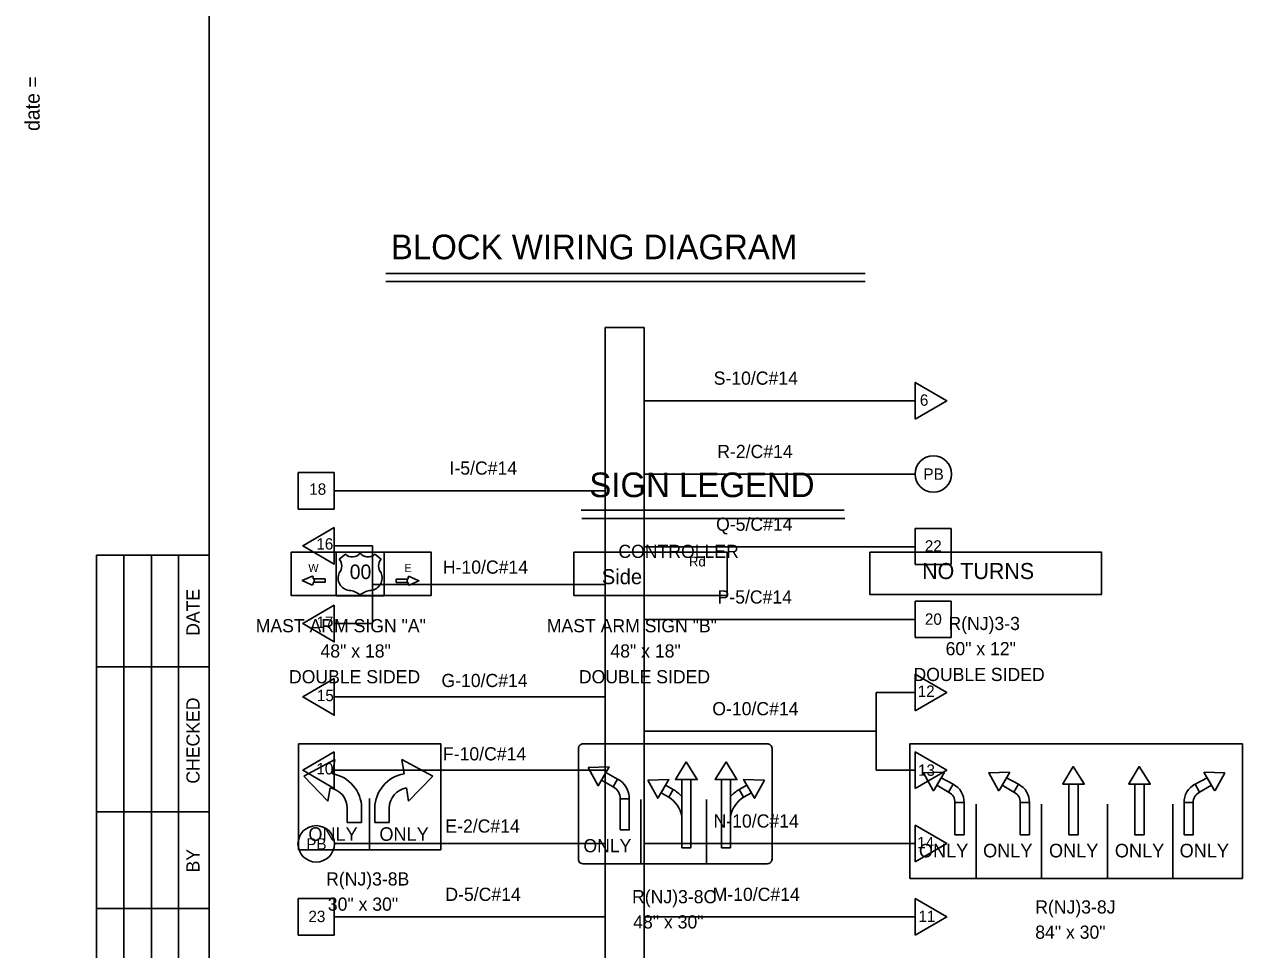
# Model space of a CAD drawing. Extents: x 488740 to 507913, y 466518 to 497949.
# Drawn here: x 507907.771 to 507908.469, y 496046.789 to 496047.319 of the extents above; entities that cross this region are included whole.
import ezdxf

# ---------------------------------------------------------------- set-up
doc = ezdxf.new("R2010")
doc.units = 0
for name, color, linetype in [('1', 7, 'Continuous'), ('25', 7, 'Continuous'), ('38', 7, 'Continuous'), ('9', 7, 'Continuous')]:
    doc.layers.add(name, color=color, linetype=linetype)

msp = doc.modelspace()

# ---------------------------------------------------------------- linework, layer by layer
at = {"layer": '1'}
for p, q in [((507907.8773, 496048.19783), (507907.8773, 496046.44783)), ((507907.8773, 496046.95965), (507907.8773, 496047.01542))]:
    msp.add_line(p, q, dxfattribs=at)
at = {"layer": '25'}
for p, q in [((507907.8773, 496047.01542), (507907.81266, 496047.01542)), ((507907.81266, 496046.44783), (507907.81266, 496047.01542)), ((507907.82841, 496046.44783), (507907.82841, 496047.01542)), ((507907.84416, 496046.44783), (507907.84416, 496047.01542)), ((507907.85958, 496046.44783), (507907.85958, 496047.01542)), ((507907.8773, 496046.95144), (507907.81266, 496046.95144)), ((507907.8773, 496046.86844), (507907.81266, 496046.86844)), ((507907.8773, 496046.81299), (507907.81266, 496046.81299))]:
    msp.add_line(p, q, dxfattribs=at)
at = {"layer": '38'}
for p, q in [((507908.0902, 496047.04115), (507908.24079, 496047.04115)), ((507908.09066, 496047.03646), (507908.24126, 496047.03646)), ((507908.08598, 496047.01712), (507908.08598, 496046.99219)), ((507908.08598, 496047.01712), (507908.17391, 496047.01712)), ((507908.08598, 496047.01712), (507908.17391, 496047.01712)), ((507908.17391, 496047.01712), (507908.17391, 496046.99219)), ((507907.95171, 496047.01307), (507907.95526, 496047.01587)), ((507907.97209, 496047.01587), (507907.97565, 496047.01307)), ((507907.96358, 496046.99215), (507907.96358, 496046.99272)), ((507907.96378, 496046.99272), (507907.96378, 496046.99215)), ((507908.08598, 496046.99219), (507908.17391, 496046.99219)), ((507907.92844, 496046.90724), (507907.92844, 496046.84654)), ((507907.92844, 496046.90724), (507908.0098, 496046.90724)), ((507908.0098, 496046.90724), (507908.0098, 496046.84654)), ((507908.08876, 496046.90497), (507908.08876, 496046.8412)), ((507908.0915, 496046.90724), (507908.19681, 496046.90724)), ((507908.19956, 496046.90465), (507908.19956, 496046.8412)), ((507908.27839, 496046.90727), (507908.46901, 496046.90727)), ((507908.27839, 496046.90727), (507908.27839, 496046.83017)), ((507908.46901, 496046.90727), (507908.46901, 496046.83017)), ((507907.9491, 496046.89839), (507907.93139, 496046.88888)), ((507907.94779, 496046.89019), (507907.9491, 496046.89839)), ((507907.9888, 496046.89019), (507907.98749, 496046.89839)), ((507907.98749, 496046.89839), (507908.00521, 496046.88888)), ((507907.93139, 496046.88888), (507907.94517, 496046.87444)), ((507908.00521, 496046.88888), (507907.99143, 496046.87444)), ((507908.10849, 496046.88272), (507908.11103, 496046.88717)), ((507908.30067, 496046.87959), (507908.30328, 496046.88416)), ((507908.33807, 496046.87959), (507908.34068, 496046.88416)), ((507908.44434, 496046.87959), (507908.44173, 496046.88416)), ((507907.94517, 496046.87444), (507907.94644, 496046.8821)), ((507907.99143, 496046.87444), (507907.99015, 496046.8821)), ((507908.14039, 496046.87677), (507908.14293, 496046.88122)), ((507908.14787, 496046.8771), (507908.14787, 496046.86576)), ((507908.1758, 496046.8771), (507908.1758, 496046.86576)), ((507908.18328, 496046.87677), (507908.18073, 496046.88122)), ((507907.95632, 496046.87051), (507907.95632, 496046.86231)), ((507907.96452, 496046.86231), (507907.96452, 496046.87051)), ((507907.96912, 496046.84654), (507907.96912, 496046.87607)), ((507907.97207, 496046.86231), (507907.97207, 496046.87051)), ((507907.98027, 496046.87051), (507907.98027, 496046.86231)), ((507908.11775, 496046.87576), (507908.11262, 496046.87576)), ((507908.12431, 496046.83867), (507908.12431, 496046.87541)), ((507908.16203, 496046.83867), (507908.16203, 496046.87541)), ((507908.30951, 496046.87366), (507908.30426, 496046.87366)), ((507908.31645, 496046.83017), (507908.31645, 496046.87282)), ((507908.34691, 496046.87366), (507908.34166, 496046.87366)), ((507908.35385, 496046.83017), (507908.35385, 496046.87282)), ((507908.39158, 496046.83017), (507908.39158, 496046.87282)), ((507908.42898, 496046.83017), (507908.42898, 496046.87282)), ((507908.43549, 496046.87366), (507908.44074, 496046.87366)), ((507908.27839, 496046.86856), (507908.27839, 496046.86856)), ((507907.95632, 496046.86231), (507907.96452, 496046.86231)), ((507907.98027, 496046.86231), (507907.97207, 496046.86231)), ((507907.92844, 496046.84654), (507908.0098, 496046.84654)), ((507908.09117, 496046.83867), (507908.19681, 496046.83867)), ((507908.27839, 496046.83017), (507908.46901, 496046.83017))]:
    msp.add_line(p, q, dxfattribs=at)
for points in [[(507907.92424, 496047.01712), (507908.00429, 496047.01712), (507908.00429, 496046.99219), (507907.92424, 496046.99219)], [(507908.2556, 496047.01712), (507908.38815, 496047.01712), (507908.38815, 496046.99284), (507908.2556, 496046.99284)], [(507907.93732, 496046.99984), (507907.93726, 496046.99984), (507907.93709, 496046.99984), (507907.93698, 496046.99978), (507907.93681, 496046.99972), (507907.93676, 496046.99967), (507907.93676, 496046.99961), (507907.9367, 496046.99866), (507907.9367, 496046.9986), (507907.93664, 496046.99854), (507907.93659, 496046.99849), (507907.93648, 496046.99843), (507907.93642, 496046.99843), (507907.93631, 496046.99832), (507907.93614, 496046.99832), (507907.93597, 496046.99832), (507907.93574, 496046.99843), (507907.93057, 496047.00079), (507907.93591, 496047.00316), (507907.93597, 496047.00321), (507907.93614, 496047.00327), (507907.93631, 496047.00327), (507907.93648, 496047.00321), (507907.93659, 496047.00316), (507907.9367, 496047.0031), (507907.93676, 496047.00299), (507907.93681, 496047.00293), (507907.93681, 496047.00203), (507907.93681, 496047.00192), (507907.93681, 496047.00186), (507907.93693, 496047.00181), (507907.93693, 496047.00181), (507907.93698, 496047.00175), (507907.93709, 496047.00175), (507907.93709, 496047.00175), (507907.93738, 496047.00175)], [(507907.99062, 496046.9998), (507907.99068, 496046.9998), (507907.99084, 496046.9998), (507907.99096, 496046.99974), (507907.99113, 496046.99969), (507907.99118, 496046.99963), (507907.99118, 496046.99957), (507907.99124, 496046.99862), (507907.99124, 496046.99856), (507907.99129, 496046.99851), (507907.99135, 496046.99845), (507907.99146, 496046.99839), (507907.99152, 496046.99839), (507907.99163, 496046.99828), (507907.9918, 496046.99828), (507907.99197, 496046.99828), (507907.99219, 496046.99839), (507907.99737, 496047.00076), (507907.99203, 496047.00312), (507907.99197, 496047.00317), (507907.9918, 496047.00323), (507907.99163, 496047.00323), (507907.99146, 496047.00317), (507907.99135, 496047.00312), (507907.99124, 496047.00306), (507907.99118, 496047.00295), (507907.99113, 496047.00289), (507907.99113, 496047.00199), (507907.99113, 496047.00188), (507907.99113, 496047.00182), (507907.99101, 496047.00177), (507907.99101, 496047.00177), (507907.99096, 496047.00171), (507907.99084, 496047.00171), (507907.99084, 496047.00171), (507907.99056, 496047.00171)], [(507907.93738, 496046.99984), (507907.94356, 496046.99984), (507907.94356, 496047.00175), (507907.93738, 496047.00175)], [(507907.99056, 496046.9998), (507907.98438, 496046.9998), (507907.98438, 496047.00171), (507907.99056, 496047.00171)], [(507908.09425, 496046.8938), (507908.09998, 496046.88335), (507908.10626, 496046.89413)], [(507908.10185, 496046.88651), (507908.10439, 496046.89096), (507908.11103, 496046.88717), (507908.10849, 496046.88272)], [(507908.15035, 496046.89708), (507908.14419, 496046.88687), (507908.15667, 496046.88686)], [(507908.17332, 496046.89708), (507908.17947, 496046.88687), (507908.16699, 496046.88686)], [(507908.29212, 496046.88055), (507908.29179, 496046.88055), (507908.28622, 496046.89072), (507908.29803, 496046.89105), (507908.29803, 496046.89072)], [(507908.32952, 496046.88055), (507908.3292, 496046.88055), (507908.32362, 496046.89072), (507908.33543, 496046.89105), (507908.33543, 496046.89072)], [(507908.36611, 496046.88415), (507908.36611, 496046.88448), (507908.37202, 496046.89433), (507908.37825, 496046.88448), (507908.37825, 496046.88415)], [(507908.40383, 496046.88415), (507908.40383, 496046.88448), (507908.40973, 496046.89433), (507908.41597, 496046.88448), (507908.41597, 496046.88415)], [(507908.45288, 496046.88055), (507908.45321, 496046.88055), (507908.45879, 496046.89072), (507908.44698, 496046.89105), (507908.44698, 496046.89072)], [(507908.12837, 496046.88658), (507908.1341, 496046.87613), (507908.14038, 496046.88691)], [(507908.13597, 496046.87929), (507908.13851, 496046.88375), (507908.14293, 496046.88122), (507908.14039, 496046.87677)], [(507908.14787, 496046.84787), (507908.153, 496046.84787), (507908.153, 496046.88686), (507908.14787, 496046.88686)], [(507908.1758, 496046.84787), (507908.17067, 496046.84787), (507908.17067, 496046.88686), (507908.1758, 496046.88686)], [(507908.1877, 496046.87929), (507908.18515, 496046.88375), (507908.18073, 496046.88122), (507908.18328, 496046.87677)], [(507908.1953, 496046.88658), (507908.18957, 496046.87613), (507908.18328, 496046.88691)], [(507908.29635, 496046.88781), (507908.30328, 496046.88416), (507908.30065, 496046.87956), (507908.2939, 496046.88358)], [(507908.33375, 496046.88781), (507908.34068, 496046.88416), (507908.33805, 496046.87956), (507908.3313, 496046.88358)], [(507908.37481, 496046.85528), (507908.36955, 496046.85528), (507908.36955, 496046.88415), (507908.37481, 496046.88415)], [(507908.41253, 496046.85528), (507908.40726, 496046.85528), (507908.40726, 496046.88415), (507908.41253, 496046.88415)], [(507908.44866, 496046.88781), (507908.44173, 496046.88416), (507908.44435, 496046.87956), (507908.4511, 496046.88358)], [(507908.11262, 496046.85804), (507908.11775, 496046.85804), (507908.11775, 496046.87576), (507908.11262, 496046.87576)], [(507908.30951, 496046.85528), (507908.30426, 496046.85528), (507908.30426, 496046.87366), (507908.30951, 496046.87366)], [(507908.34691, 496046.85528), (507908.34166, 496046.85528), (507908.34166, 496046.87366), (507908.34691, 496046.87366)], [(507908.43549, 496046.85528), (507908.44074, 496046.85528), (507908.44074, 496046.87366), (507908.43549, 496046.87366)]]:
    msp.add_lwpolyline(points, close=True, dxfattribs=at)
msp.add_lwpolyline([(507907.96378, 496046.99215), (507907.97746, 496046.99215), (507907.97746, 496047.01708), (507907.9499, 496047.01708), (507907.9499, 496046.99215), (507907.96358, 496046.99215)], dxfattribs=at)
for centre, radius, start, end in [((507907.95912, 496047.01988), 0.00557, 226.13784, 324.97605), ((507907.96823, 496047.01988), 0.00557, 215.02395, 313.86216), ((507907.94725, 496047.00918), 0.00591, 318.96758, 41.03242), ((507907.98011, 496047.00918), 0.00591, 138.96758, 221.03243), ((507907.95832, 496047.00237), 0.00724, 156.10933, 263.19699), ((507907.96903, 496047.00237), 0.00724, 276.80301, 23.89067), ((507907.95657, 496046.98417), 0.01105, 50.63578, 85.32525), ((507907.97079, 496046.98417), 0.01105, 94.67475, 129.36423), ((507908.09116, 496046.90487), 0.00241, 84.73874, 177.63311), ((507908.19688, 496046.9046), 0.00268, 1.08904, 93.98033), ((507907.94432, 496046.87028), 0.02021, 0.63274, 80.09634), ((507907.99228, 496046.87028), 0.02021, 99.90366, 179.36726), ((507908.10521, 496046.87606), 0.01255, 358.62032, 62.31163), ((507908.29803, 496046.87394), 0.01148, 358.57482, 62.82463), ((507908.33544, 496046.87394), 0.01148, 358.57482, 62.82463), ((507908.44697, 496046.87394), 0.01148, 117.17537, 181.42518), ((507907.94432, 496046.87028), 0.01201, 0.63274, 79.7949), ((507907.99228, 496046.87028), 0.01201, 100.2051, 179.36726), ((507908.10495, 496046.87591), 0.00767, 358.83551, 62.52682), ((507908.13199, 496046.86302), 0.01611, 9.7849, 58.59208), ((507908.13185, 496046.86293), 0.02138, 41.49862, 58.79284), ((507908.19181, 496046.86293), 0.02138, 121.20716, 138.50138), ((507908.19167, 496046.86302), 0.01611, 121.40792, 170.2151), ((507908.29803, 496046.87394), 0.00623, 357.37479, 64.99082), ((507908.33544, 496046.87394), 0.00623, 357.37479, 64.99082), ((507908.44697, 496046.87394), 0.00623, 115.00918, 182.62521), ((507908.09109, 496046.84104), 0.00234, 176.13508, 269.02944), ((507908.19691, 496046.84135), 0.00266, 265.44951, 356.72662)]:
    msp.add_arc(centre, radius, start, end, dxfattribs=at)
at = {"layer": '9'}
for p, q in [((507907.97847, 496047.17673), (507908.25279, 496047.17673)), ((507907.97847, 496047.17218), (507908.25279, 496047.17218)), ((507908.104, 496047.1458), (507908.104, 496046.55381)), ((507908.104, 496047.1458), (507908.12631, 496047.1458)), ((507908.12631, 496047.1458), (507908.12631, 496046.55381)), ((507908.12631, 496047.1038), (507908.2815, 496047.1038)), ((507907.92815, 496047.06279), (507907.94882, 496047.06279)), ((507907.92815, 496047.0418), (507907.92815, 496047.06279)), ((507907.94882, 496047.06279), (507907.94882, 496047.0418)), ((507908.12631, 496047.06181), (507908.2815, 496047.06181)), ((507907.94882, 496047.05229), (507908.104, 496047.05229)), ((507907.94882, 496047.0418), (507907.92815, 496047.0418)), ((507908.2815, 496047.03064), (507908.30217, 496047.03064)), ((507908.2815, 496047.00997), (507908.2815, 496047.03064)), ((507908.30217, 496047.03064), (507908.30217, 496047.00997)), ((507907.94882, 496047.0208), (507907.9708, 496047.0208)), ((507907.9708, 496047.0208), (507907.9708, 496046.97618)), ((507908.12631, 496047.02014), (507908.2815, 496047.02014)), ((507908.30217, 496047.00997), (507908.2815, 496047.00997)), ((507907.9708, 496046.99849), (507908.104, 496046.99849)), ((507908.2815, 496046.98897), (507908.30217, 496046.98897)), ((507908.2815, 496046.9683), (507908.2815, 496046.98897)), ((507908.30217, 496046.98897), (507908.30217, 496046.9683)), ((507907.94882, 496046.97618), (507907.9708, 496046.97618)), ((507908.12631, 496046.97847), (507908.2815, 496046.97847)), ((507908.30217, 496046.9683), (507908.2815, 496046.9683)), ((507907.94882, 496046.93418), (507908.104, 496046.93418)), ((507908.25919, 496046.93681), (507908.25919, 496046.89219)), ((507908.25919, 496046.93681), (507908.2815, 496046.93681)), ((507908.25919, 496046.9145), (507908.12631, 496046.9145)), ((507907.94882, 496046.89219), (507908.104, 496046.89219)), ((507908.25919, 496046.89219), (507908.2815, 496046.89219)), ((507907.94882, 496046.85019), (507908.104, 496046.85019)), ((507908.12631, 496046.85019), (507908.2815, 496046.85019)), ((507907.92815, 496046.8187), (507907.94882, 496046.8187)), ((507907.92815, 496046.7977), (507907.92815, 496046.8187)), ((507907.94882, 496046.8187), (507907.94882, 496046.7977)), ((507907.94882, 496046.8082), (507908.104, 496046.8082)), ((507908.12631, 496046.8082), (507908.2815, 496046.8082)), ((507907.94882, 496046.7977), (507907.92815, 496046.7977))]:
    msp.add_line(p, q, dxfattribs=at)
for points in [[(507908.2815, 496047.0933), (507908.29954, 496047.1038), (507908.2815, 496047.1143), (507908.2815, 496047.0933)], [(507907.94882, 496047.0313), (507907.93077, 496047.0208), (507907.94882, 496047.0103), (507907.94882, 496047.0313)], [(507907.94882, 496046.98668), (507907.93077, 496046.97618), (507907.94882, 496046.96568), (507907.94882, 496046.98668)], [(507908.2815, 496046.92631), (507908.29954, 496046.93681), (507908.2815, 496046.94731), (507908.2815, 496046.92631)], [(507907.94882, 496046.94468), (507907.93077, 496046.93418), (507907.94882, 496046.92368), (507907.94882, 496046.94468)], [(507907.94882, 496046.90269), (507907.93077, 496046.89219), (507907.94882, 496046.88169), (507907.94882, 496046.90269)], [(507908.2815, 496046.88169), (507908.29954, 496046.89219), (507908.2815, 496046.90269), (507908.2815, 496046.88169)], [(507908.2815, 496046.8397), (507908.29954, 496046.85019), (507908.2815, 496046.86069), (507908.2815, 496046.8397)], [(507908.2815, 496046.7977), (507908.29954, 496046.8082), (507908.2815, 496046.8187), (507908.2815, 496046.7977)]]:
    msp.add_lwpolyline(points, dxfattribs=at)
for centre in [(507908.29193, 496047.06181), (507907.93852, 496046.85006)]:
    msp.add_circle(centre, 0.01043, dxfattribs=at)

# ---------------------------------------------------------------- texts
at = {"layer": '1'}
for s, height, p in [('.......time......', 0.0001201, (507907.78018, 496047.31506)), ('date =', 0.008335, (507907.78018, 496047.2583))]:
    msp.add_text(s, height=height, rotation=90, dxfattribs=at).set_placement(p)
at = {"layer": '25'}
for s, p in [('DATE', (507907.87172, 496046.96916)), ('CHECKED', (507907.87172, 496046.88451)), ('BY', (507907.87172, 496046.83366))]:
    msp.add_text(s, height=0.007545, rotation=90, dxfattribs=at).set_placement(p)
at = {"layer": '38'}
for s, height, p in [('SIGN LEGEND', 0.0141083, (507908.09493, 496047.0486)), ('W', 0.00468, (507907.93399, 496047.00573)), ('00', 0.008313, (507907.9577, 496047.0017)), ('E', 0.00468, (507907.989, 496047.00569)), ('Rd', 0.005634, (507908.15193, 496047.00892)), ('NO TURNS', 0.009187, (507908.28546, 496047.0017)), ('Side', 0.008624, (507908.10206, 496046.99875)), ('MAST ARM SIGN "A"', 0.0075453, (507907.90389, 496046.97119)), ('MAST ARM SIGN "B"', 0.0075453, (507908.07056, 496046.97119)), ('R(NJ)3-3', 0.007545, (507908.30055, 496046.9725)), ('48" x 18"', 0.007545, (507907.94097, 496046.95675)), ('48" x 18"', 0.007545, (507908.10698, 496046.95675)), ('60" x 12"', 0.007545, (507908.29891, 496046.95807)), ('DOUBLE SIDED', 0.0075453, (507907.92292, 496046.94199)), ('DOUBLE SIDED', 0.0075453, (507908.08893, 496046.94199)), ('DOUBLE SIDED', 0.0075453, (507908.28053, 496046.9433)), ('ONLY', 0.007762, (507907.93402, 496046.85179)), ('ONLY', 0.007762, (507907.9747, 496046.85179)), ('ONLY', 0.007545, (507908.0915, 496046.84523)), ('ONLY', 0.007762, (507908.28364, 496046.84231)), ('ONLY', 0.007762, (507908.32038, 496046.84231)), ('ONLY', 0.007762, (507908.35811, 496046.84231)), ('ONLY', 0.007762, (507908.39584, 496046.84231)), ('ONLY', 0.007762, (507908.43292, 496046.84231)), ('R(NJ)3-8B', 0.007545, (507907.94419, 496046.8262)), ('R(NJ)3-8C', 0.007545, (507908.11938, 496046.81603)), ('30" x 30"', 0.007545, (507907.94517, 496046.81177)), ('R(NJ)3-8J', 0.007545, (507908.35024, 496046.81016)), ('48" x 30"', 0.007545, (507908.12004, 496046.80159)), ('84" x 30"', 0.007545, (507908.35024, 496046.79572))]:
    msp.add_text(s, height=height, dxfattribs=at).set_placement(p)
at = {"layer": '9'}
for s, height, p in [('BLOCK WIRING DIAGRAM', 0.0141083, (507907.9813, 496047.18484)), ('S-10/C#14', 0.007545, (507908.16611, 496047.11299)), ('6', 0.00651, (507908.28419, 496047.10096)), ('R-2/C#14', 0.007545, (507908.16818, 496047.07099)), ('I-5/C#14', 0.007545, (507908.01486, 496047.06148)), ('PB', 0.00651, (507908.28625, 496047.05855)), ('18', 0.00651, (507907.93456, 496047.04995)), ('Q-5/C#14', 0.007545, (507908.16749, 496047.02933)), ('16', 0.00651, (507907.93861, 496047.01856)), ('22', 0.00651, (507908.28702, 496047.0174)), ('CONTROLLER', 0.007545, (507908.11155, 496047.01378)), ('H-10/C#14', 0.007545, (507908.01104, 496047.00477)), ('P-5/C#14', 0.007545, (507908.16834, 496046.98766)), ('20', 0.00651, (507908.28707, 496046.97552)), ('17', 0.00651, (507907.93864, 496046.97372)), ('G-10/C#14', 0.007545, (507908.01023, 496046.93985)), ('12', 0.00651, (507908.28294, 496046.93422)), ('15', 0.00651, (507907.93893, 496046.93177)), ('O-10/C#14', 0.007545, (507908.16533, 496046.92368)), ('F-10/C#14', 0.007545, (507908.0111, 496046.89785)), ('10', 0.00651, (507907.93861, 496046.88983)), ('13', 0.00651, (507908.28312, 496046.88903)), ('E-2/C#14', 0.007545, (507908.01247, 496046.85648)), ('N-10/C#14', 0.007545, (507908.16606, 496046.85938)), ('PB', 0.00651, (507907.93283, 496046.8468)), ('14', 0.00651, (507908.28264, 496046.84753)), ('D-5/C#14', 0.007545, (507908.01247, 496046.81739)), ('M-10/C#14', 0.007545, (507908.16551, 496046.81739)), ('23', 0.00651, (507907.93406, 496046.80525)), ('11', 0.00651, (507908.2834, 496046.80532))]:
    msp.add_text(s, height=height, dxfattribs=at).set_placement(p)

doc.saveas('drawing.dxf')
